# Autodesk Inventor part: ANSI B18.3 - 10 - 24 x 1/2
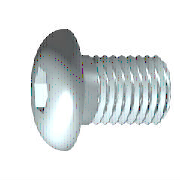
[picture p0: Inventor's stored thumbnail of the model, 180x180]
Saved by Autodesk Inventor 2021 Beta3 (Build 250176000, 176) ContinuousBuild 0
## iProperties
Created: 2013-02
Part Number: ANSI B18.3 - 10 - 24 x 1/2
Material: Generic
Description: Hexagon Socket Button Head Cap Screw
Document SubType Name: Modeling
Standard: ANSI B18.3
Designer: John
Standard Revision: 2003
Standards Organization: ANSI
Language: en-US
Size Designation: 10 - 24 x 1/2
Categories: <MemberInstance><Categories><Category DisplayName="Fasteners" InternalName="e4da775c-781d-43d5-af7c-5136215cf5a6" Mnemonic="FSTN"><Category DisplayName="Bolts"
Density: 1 g/cm^3
Appearance: Default
IsCustomPart: 0
Author: John
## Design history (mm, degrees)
sketch "Sketch1"
  geometry: L1 (0.271, 0)-(12.7, 0); L2 (12.7, 0)-(12.7, 2.413); L3 (12.7, 2.413)-(2.108, 2.413); L4 (2.108, 2.413)-(0, 2.413); L5 (0, 2.413)-(0, 2.413); L6 (0, 2.413)-(0, 4.585); L7 (0, 4.585)-(-2.565, 4.585); L8 (-2.565, 4.585)-(-2.565, 1.833); L9 (-2.565, 1.833)-(-0.787, 1.833); L10 (-0.787, 1.833)-(0.271, 0); L11 (-5.618, 0)-(15.753, 0) reference; L12 (0, -0.917)-(0, 5.502) reference; L13 (2.108, 2.413)-(0, 2.413)
  constraints: 22 end point, 6 parallel, 2 collinear, 2 perpendicular, 1 horizontal, 1 point on line
  dimensions: "d1" = 10.5916 distance from line of L3.end L2 (= GEL); "d2" = 2.1083 distance of L4.end L3.end (computed from GAL); "d3" = 2.5654 distance between parallel lines of L8 L6 (= KOH); "d4" = 1.778 distance of L8.end L9.end (= INTI); "d5" = 60 deg angle of L10 L1; "d6" = 4.826 diameter of L3 L1 (= GD); "d7" = 4.826 diameter of L5 L1 (= BDM); "d8" = 3.66617 diameter of L9 L1 (= 1.1547 x SW); "d9" = 9.1694 diameter of L7 L1 (= KOD); "d26" = 12.7 distance between parallel lines of L12 L2 (= NLG)
revolve "Body" sketch "Sketch1" stored, may be unused: angle "d10" = 90 deg
sketch "Sketch2"
  geometry: L1 (0, -6.419)-(0, 6.419) reference; L2 (-6.419, 0)-(6.419, 0) reference; L3 (1.833, 0)-(0.917, -1.587); L4 (0.917, -1.587)-(-0.917, -1.588); L5 (-0.917, -1.588)-(-1.833, 0); L6 (-1.833, 0)-(-0.917, 1.587); L7 (-0.917, 1.587)-(0.917, 1.588); L8 (0.917, 1.588)-(1.833, 0); 2 further points
  constraints: 12 end point, 1 coincident, 1 horizontal alignment, 1 point on line, 12 other
extrude "Slot" join sketch "Sketch2" stored distance "d11" = 10; taper "d12" = 0 deg
workplane "Work Plane1"
fillet "Fillet2" dims "d30" = 0.1 (= R)
body "Solid1"
fillet "Fillet1" dims "d17" = 2.3114 (= RR)
feature "Thread" dims "d13" = 10.5916 (= GEL), "d14" = 0
chamfer "Chamfer1" distance "d15" = 0.64922 (= -0.5 x SPD + 0.5 x GD); stored, may be unused: second distance "d16" = 0.64922 (= GUL), angle "d27" = 45 deg
other parameters: "GD" = 4.826 (= NND) [user parameter; used in 2 equation terms], "NLG" = 12.7 [user parameter; used in 1 equation term], "GEL" = 10.5916 [user parameter; used in 2 equation terms], "KOD" = 9.1694 [user parameter; used in 1 equation term], "KOH" = 2.5654 [user parameter; used in 1 equation term], "INTI" = 1.778 [user parameter; used in 1 equation term], "GAL" = 2.1082 [user parameter; used in 1 equation term], "GUL" = 0.64922 [user parameter; used in 1 equation term], "BDM" = 4.826 (= NND) [user parameter; used in 1 equation term], "SW" = 3.175 [user parameter; used in 1 equation term], "RR" = 2.3114 [user parameter; used in 1 equation term], "SPD" = 3.52755 [user parameter; used in 2 equation terms], "d19" = 0, "d28" = 0, "d29" = 0, "R" = 0.1 [user parameter; used in 1 equation term], "TOA" = 30 deg [user parameter], "GD1" = 3.52755 (= SPD) [user parameter], "THREADDIA" = 4.826 [user parameter], "PTC" = 1.05833 (computed from TPU) [user parameter], "KOH1" = 0.508 [user parameter], "NND" = 4.826 [user parameter; used in 2 equation terms], "E0" = 3.66725 [user parameter]
